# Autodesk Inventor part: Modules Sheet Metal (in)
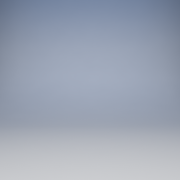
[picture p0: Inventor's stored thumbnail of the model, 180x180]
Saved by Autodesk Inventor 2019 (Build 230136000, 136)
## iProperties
Created: 2014-08
Part Number: Modules Sheet Metal (in)
Material: Generic
Document SubType Name: Sheet Metal
Designer: Wally
Density: 1 g/cm^3
Sheet Metal Rule: Default
Appearance: Default
Author: Wally
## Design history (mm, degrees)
node "Sketch1"
other parameters: "Thickness" = 3.048, "BendRadius" = 3.048 (= Thickness), "BendReliefWidth" = 3.048 (= Thickness), "BendReliefDepth" = 1.524 (= 0.5 x Thickness), "CornerReliefSize" = 12.192 (= 4 x Thickness), "SeamGap" = 0.01, "MinimumRemnant" = 6.096 (= 2 x Thickness), "TransitionRadius" = 3.048 (= BendRadius), "JacobiRadiusSize" = 3.048 (= Thickness), "GapSize" = 3.048 (= Thickness)
